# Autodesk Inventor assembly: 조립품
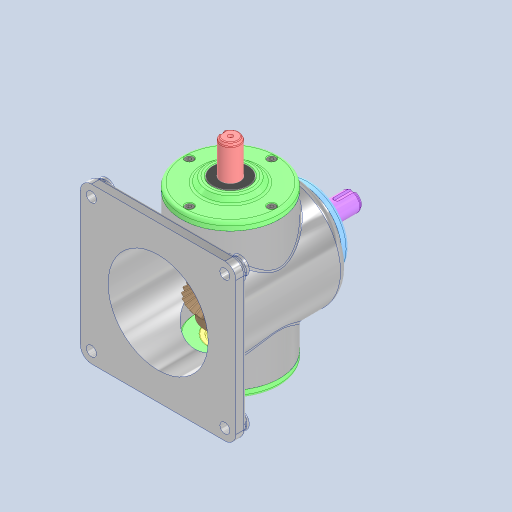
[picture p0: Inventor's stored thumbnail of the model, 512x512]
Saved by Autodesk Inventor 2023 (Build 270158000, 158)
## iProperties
Created: 2025-05
Part Number: 조립품
Document SubType Name: Assembly
Designer: Admin
Author: Admin
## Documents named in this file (13)
- C:\Users\Admin\Desktop\750505V1005\조립품.iam
- C:\Users\Admin\Desktop\750505V1005\본체.ipt
- C:\Users\Admin\Desktop\750505V1005\측면 커버.ipt
- C:\Users\Admin\Desktop\750505V1005\깊은 홈 볼 베어링 6203.ipt
- C:\Users\Admin\Desktop\750505V1005\오일 실 17 32 8.ipt
- C:\Users\Admin\Desktop\750505V1005\메인 축.ipt
- C:\Users\Admin\Desktop\750505V1005\평행 키 5x5.ipt
- C:\Users\Admin\Desktop\750505V1005\메인 베벨기어.ipt
- C:\Users\Admin\Desktop\750505V1005\6각 구멍붙이 볼트 M4-10L.ipt
- C:\Users\Admin\Desktop\750505V1005\윗 커버.ipt
- C:\Users\Admin\Desktop\750505V1005\서브 축.ipt
- C:\Users\Admin\Desktop\750505V1005\평행 키 4x4.ipt
- C:\Users\Admin\Desktop\750505V1005\서브 베벨기어.ipt
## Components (12 placed, 1 different names)
1. 6각 구멍붙이 볼트 M4-10L:1
2. 6각 구멍붙이 볼트 M4-10L:2
3. 6각 구멍붙이 볼트 M4-10L:3
4. 6각 구멍붙이 볼트 M4-10L:4
5. 6각 구멍붙이 볼트 M4-10L:5
6. 6각 구멍붙이 볼트 M4-10L:6
7. 6각 구멍붙이 볼트 M4-10L:7
8. 6각 구멍붙이 볼트 M4-10L:8
9. 6각 구멍붙이 볼트 M4-10L:9
10. 6각 구멍붙이 볼트 M4-10L:10
11. 6각 구멍붙이 볼트 M4-10L:11
12. 6각 구멍붙이 볼트 M4-10L:12
